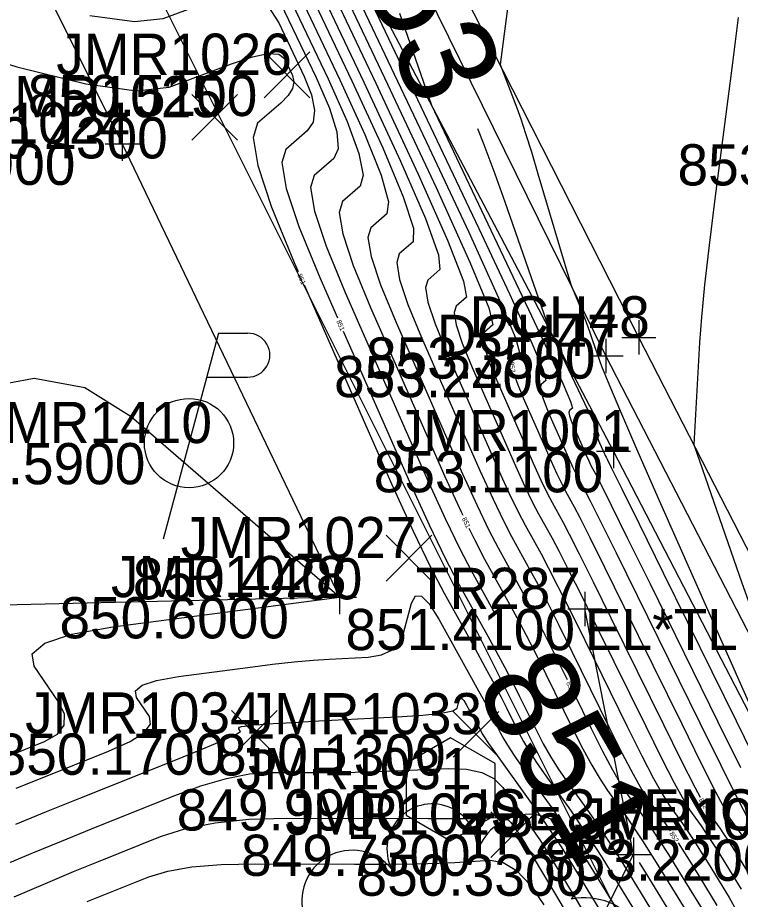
# Model space of a CAD drawing. Extents: x 1654928 to 1810050, y 486881 to 626330.
# Drawn here: x 1801396.23 to 1801417.31, y 489814.52 to 489840.21 of the extents above; entities that cross this region are included whole.
import ezdxf

# ---------------------------------------------------------------- set-up
doc = ezdxf.new("R2010")
doc.units = 0
for name, color, linetype in [('DT_X_Contour_Major', 7, 'Continuous'), ('DT_X_Contour_Minor', 7, 'Continuous'), ('PV_X_EOP', 7, 'Continuous'), ('PV_X_Shoulder', 7, 'Continuous'), ('RD_X_Cells', 7, 'Continuous'), ('RD_X_Fence', 7, 'Continuous'), ('RW_X_Esmt_SH', 7, 'Continuous'), ('SV_X_Break_Lines', 7, 'Continuous'), ('SV_X_Random_Point', 7, 'Continuous'), ('SV_X_Shot_Marker', 7, 'Continuous'), ('SV_X_Text_Comment', 7, 'Continuous'), ('SV_X_Text_Elevation', 7, 'Continuous'), ('SV_X_Text_Name', 7, 'Continuous'), ('UT_X_Electric_Cells', 7, 'Continuous'), ('UT_X_Telecom', 7, 'Continuous'), ('VG_X_Cells', 7, 'Continuous')]:
    doc.layers.add(name, color=color, linetype=linetype)

msp = doc.modelspace()

# ---------------------------------------------------------------- linework, layer by layer
at = {"layer": 'DT_X_Contour_Major'}
for points in [[(1801402.845, 489846.354), (1801406.672, 489838.301), (1801407.913, 489835.647), (1801408.768, 489833.723), (1801409.235, 489832.53), (1801409.316, 489832.067), (1801409.015, 489831.806), (1801408.96, 489831.621), (1801409.021, 489831.26), (1801409.197, 489830.724), (1801409.49, 489830.013), (1801410.425, 489827.883), (1801410.75, 489827.151), (1801411.025, 489826.552), (1801411.248, 489826.086), (1801411.422, 489825.753), (1801411.816, 489825.042), (1801412.01, 489824.677), (1801412.298, 489824.115), (1801412.678, 489823.356), (1801413.151, 489822.399), (1801414.537, 489819.586), (1801415.007, 489818.641), (1801415.379, 489817.916), (1801415.652, 489817.412), (1801415.826, 489817.127), (1801416.159, 489816.662), (1801416.292, 489816.47), (1801416.444, 489816.241), (1801416.614, 489815.975), (1801416.802, 489815.672), (1801417.327, 489814.817)], [(1801403.678, 489841.112), (1801404.937, 489838.464), (1801405.323, 489837.572), (1801405.537, 489836.882), (1801405.58, 489836.393), (1801405.451, 489836.107), (1801404.879, 489835.612), (1801404.774, 489835.259), (1801404.89, 489834.574), (1801405.226, 489833.555), (1801405.782, 489832.203), (1801407.559, 489828.154), (1801408.177, 489826.762), (1801408.699, 489825.623), (1801409.125, 489824.737), (1801409.454, 489824.104), (1801410.15, 489822.85)], [(1801409.638, 489836.984), (1801409.823, 489836.512), (1801410.145, 489835.658), (1801410.436, 489834.847), (1801411.723, 489831.16), (1801412.759, 489828.98), (1801412.952, 489828.57), (1801413.087, 489828.275), (1801413.163, 489828.094), (1801413.181, 489828.027), (1801413.151, 489828.001), (1801413.145, 489827.983), (1801413.152, 489827.947), (1801413.169, 489827.894), (1801413.198, 489827.823), (1801413.291, 489827.612), (1801413.323, 489827.54), (1801413.35, 489827.48), (1801413.372, 489827.434), (1801413.389, 489827.401), (1801413.429, 489827.331), (1801413.541, 489827.105), (1801413.849, 489826.481), (1801414.353, 489825.459), (1801415.053, 489824.039), (1801417.18, 489819.721), (1801417.881, 489818.3)], [(1801395.757, 489815.49), (1801396.632, 489815.859), (1801397.51, 489816.221), (1801398.389, 489816.577), (1801400.738, 489817.517), (1801401.576, 489817.826), (1801402.326, 489818.046), (1801402.989, 489818.177), (1801403.566, 489818.22), (1801404.987, 489818.217), (1801405.527, 489818.219), (1801406.079, 489818.228), (1801406.645, 489818.243), (1801407.223, 489818.265), (1801408.782, 489818.332), (1801409.321, 489818.316), (1801409.766, 489818.22), (1801410.119, 489818.044), (1801410.379, 489817.786), (1801410.947, 489816.991), (1801411.148, 489816.708), (1801411.324, 489816.452), (1801411.474, 489816.225), (1801411.6, 489816.027), (1801412.042, 489815.305), (1801412.236, 489814.982), (1801412.484, 489814.567), (1801414.318, 489811.48)], [(1801414.354, 489815.595), (1801414.607, 489815.188), (1801415.563, 489813.631)]]:
    msp.add_lwpolyline(points, dxfattribs=at)
at = {"layer": 'DT_X_Contour_Minor'}
for points in [[(1801401.454, 489850.675), (1801408.141, 489836.605), (1801409.386, 489833.96), (1801410.254, 489832.052), (1801410.746, 489830.882), (1801410.862, 489830.451), (1801410.669, 489830.284), (1801410.655, 489830.236)], [(1801402.678, 489847.402), (1801407.019, 489838.269), (1801408.431, 489835.262), (1801409.414, 489833.091), (1801409.967, 489831.757), (1801410.089, 489831.259), (1801409.842, 489831.045), (1801409.797, 489830.893), (1801409.847, 489830.598), (1801409.992, 489830.158), (1801410.232, 489829.575), (1801410.998, 489827.829), (1801411.265, 489827.228), (1801411.49, 489826.737), (1801411.673, 489826.355), (1801411.815, 489826.082), (1801412.139, 489825.5), (1801412.317, 489825.163), (1801412.608, 489824.588), (1801413.013, 489823.777), (1801413.532, 489822.727), (1801415.066, 489819.613), (1801415.582, 489818.573), (1801415.981, 489817.788), (1801416.132, 489817.503)], [(1801403.012, 489845.306), (1801406.325, 489838.334), (1801407.395, 489836.032), (1801408.122, 489834.355), (1801408.504, 489833.302), (1801408.543, 489832.875), (1801408.188, 489832.567), (1801408.123, 489832.349), (1801408.194, 489831.923), (1801408.403, 489831.291), (1801408.748, 489830.451), (1801409.852, 489827.937), (1801410.235, 489827.073), (1801410.559, 489826.366), (1801410.824, 489825.816), (1801411.028, 489825.423), (1801411.494, 489824.585), (1801411.704, 489824.192), (1801411.987, 489823.642), (1801412.343, 489822.935), (1801412.771, 489822.071), (1801414.008, 489819.559), (1801414.433, 489818.709), (1801414.777, 489818.044), (1801415.042, 489817.564), (1801415.227, 489817.269), (1801415.614, 489816.728), (1801415.77, 489816.504), (1801415.947, 489816.237), (1801416.144, 489815.927), (1801416.363, 489815.575), (1801416.974, 489814.58), (1801417.187, 489814.207)], [(1801411.036, 489844.506), (1801410.3, 489838.843), (1801410.785, 489837.583), (1801410.902, 489837.26), (1801411.043, 489836.832), (1801411.211, 489836.298), (1801411.403, 489835.659), (1801412.362, 489832.432), (1801412.67, 489831.685), (1801412.74, 489831.51), (1801412.818, 489831.305), (1801412.904, 489831.071), (1801412.998, 489830.806), (1801413.259, 489830.06), (1801413.437, 489829.606), (1801413.777, 489828.802), (1801414.278, 489827.649), (1801414.941, 489826.147), (1801418.411, 489818.322)], [(1801403.178, 489844.257), (1801405.978, 489838.367), (1801406.877, 489836.417), (1801407.476, 489834.987), (1801407.773, 489834.075), (1801407.77, 489833.683), (1801407.36, 489833.328), (1801407.285, 489833.076), (1801407.368, 489832.586), (1801407.609, 489831.857), (1801408.007, 489830.889), (1801409.278, 489827.991), (1801409.721, 489826.995), (1801410.094, 489826.18), (1801410.399, 489825.546), (1801410.635, 489825.093), (1801411.171, 489824.127), (1801411.398, 489823.706), (1801411.677, 489823.169), (1801412.008, 489822.514), (1801412.39, 489821.743), (1801413.48, 489819.532), (1801413.858, 489818.777), (1801414.175, 489818.172), (1801414.432, 489817.716), (1801414.628, 489817.41), (1801415.07, 489816.793), (1801415.247, 489816.537), (1801415.257, 489816.522)], [(1801404.877, 489844.17), (1801409.68, 489834.064), (1801410.574, 489832.163), (1801411.198, 489830.793), (1801411.552, 489829.953), (1801411.635, 489829.643), (1801411.496, 489829.523), (1801411.471, 489829.438), (1801411.499, 489829.272), (1801411.58, 489829.026), (1801411.715, 489828.699), (1801412.144, 489827.72), (1801412.294, 489827.384), (1801412.42, 489827.109), (1801412.523, 489826.895), (1801412.602, 489826.742), (1801412.784, 489826.415), (1801412.929, 489826.134), (1801413.229, 489825.535), (1801413.683, 489824.618), (1801416.123, 489819.667), (1801416.731, 489818.437), (1801417.184, 489817.532), (1801417.481, 489816.954)], [(1801403.345, 489843.209), (1801405.631, 489838.399), (1801406.359, 489836.802), (1801406.83, 489835.618), (1801407.042, 489834.848), (1801406.997, 489834.491), (1801406.533, 489834.089), (1801406.448, 489833.804), (1801406.542, 489833.248), (1801406.814, 489832.423), (1801407.265, 489831.327), (1801408.705, 489828.046), (1801409.206, 489826.917), (1801409.629, 489825.994), (1801409.974, 489825.276), (1801410.241, 489824.764), (1801410.849, 489823.669), (1801411.092, 489823.221), (1801411.367, 489822.695), (1801411.673, 489822.094), (1801412.01, 489821.415), (1801412.251, 489820.927)], [(1801403.512, 489842.161), (1801405.284, 489838.432), (1801405.841, 489837.187), (1801406.184, 489836.25), (1801406.311, 489835.621), (1801406.224, 489835.299), (1801405.706, 489834.851), (1801405.611, 489834.532), (1801405.716, 489833.911), (1801406.02, 489832.989), (1801406.523, 489831.765), (1801408.132, 489828.1), (1801408.692, 489826.84), (1801409.164, 489825.809), (1801409.211, 489825.712)], [(1801386.203, 489842.133), (1801393.676, 489839.584), (1801396.214, 489838.78), (1801398.222, 489838.279), (1801399.7, 489838.08), (1801400.648, 489838.185), (1801402.471, 489838.868), (1801403.08, 489839.07), (1801403.54, 489839.161), (1801403.85, 489839.143), (1801404.012, 489839.016), (1801404.243, 489838.529), (1801404.287, 489838.342), (1801404.245, 489838.145), (1801404.118, 489837.939), (1801403.905, 489837.723), (1801403.224, 489837.134), (1801403.1, 489836.715), (1801403.237, 489835.899), (1801403.637, 489834.687), (1801404.299, 489833.079), (1801404.416, 489832.813)], [(1801398.342, 489840.27), (1801399.643, 489840.095), (1801400.478, 489840.187), (1801402.083, 489840.789)], [(1801403.525, 489840.55), (1801403.845, 489840.064), (1801404.59, 489838.497), (1801404.805, 489837.957), (1801404.891, 489837.514), (1801404.849, 489837.166), (1801404.678, 489836.915), (1801404.051, 489836.373), (1801403.937, 489835.987), (1801404.064, 489835.237), (1801404.431, 489834.121), (1801405.04, 489832.641), (1801405.556, 489831.466)], [(1801407.365, 489840.342), (1801408.3, 489837.665), (1801411.22, 489831.522), (1801411.763, 489830.367), (1801412.142, 489829.534), (1801412.357, 489829.023), (1801412.408, 489828.835), (1801412.324, 489828.762), (1801412.308, 489828.71), (1801412.325, 489828.609), (1801412.375, 489828.46), (1801412.456, 489828.261), (1801412.717, 489827.666), (1801412.808, 489827.462), (1801412.885, 489827.294), (1801412.948, 489827.164), (1801412.996, 489827.071), (1801413.106, 489826.873), (1801413.235, 489826.62), (1801413.539, 489826.008), (1801414.018, 489825.039), (1801414.673, 489823.711), (1801416.651, 489819.694), (1801417.306, 489818.368)], [(1801417.236, 489840.216), (1801417.068, 489838.815), (1801416.563, 489834.932), (1801416.393, 489833.578), (1801416.261, 489832.429), (1801416.168, 489831.486), (1801416.113, 489830.747), (1801415.947, 489827.777), (1801417.104, 489824.439), (1801417.348, 489823.746), (1801417.583, 489823.097), (1801417.811, 489822.491), (1801418.03, 489821.93), (1801419.035, 489819.412), (1801421.198, 489814.495)], [(1801404.584, 489832.428), (1801406.412, 489828.262), (1801407.148, 489826.606), (1801407.769, 489825.252), (1801408.275, 489824.198), (1801408.667, 489823.445), (1801409.559, 489821.839), (1801409.868, 489821.278), (1801410.126, 489820.803), (1801410.333, 489820.411), (1801410.489, 489820.104), (1801410.837, 489819.396), (1801410.985, 489819.118), (1801411.167, 489818.812), (1801411.383, 489818.478), (1801411.634, 489818.118), (1801412.348, 489817.12), (1801412.628, 489816.718), (1801412.932, 489816.261), (1801413.261, 489815.749), (1801413.613, 489815.183), (1801414.586, 489813.598)], [(1801405.725, 489831.081), (1801406.986, 489828.208), (1801407.662, 489826.684), (1801408.234, 489825.437), (1801408.7, 489824.467), (1801409.06, 489823.775), (1801409.881, 489822.296), (1801410.174, 489821.764), (1801410.436, 489821.276), (1801410.668, 489820.832), (1801410.869, 489820.432), (1801411.366, 489819.424), (1801411.559, 489819.05), (1801411.769, 489818.684), (1801411.993, 489818.326), (1801412.233, 489817.976), (1801412.893, 489817.054), (1801413.158, 489816.672), (1801413.459, 489816.218), (1801413.796, 489815.69), (1801414.168, 489815.091), (1801415.553, 489812.833)], [(1801410.708, 489829.828), (1801410.786, 489829.592), (1801410.973, 489829.137), (1801411.571, 489827.775), (1801411.779, 489827.306), (1801411.955, 489826.923), (1801412.098, 489826.625), (1801412.209, 489826.412), (1801412.461, 489825.958), (1801412.623, 489825.648), (1801412.918, 489825.062), (1801413.348, 489824.197), (1801413.912, 489823.055), (1801415.594, 489819.64), (1801416.157, 489818.505), (1801416.582, 489817.66), (1801416.871, 489817.107), (1801417.024, 489816.844), (1801417.247, 489816.532), (1801417.337, 489816.402)], [(1801394.166, 489817.962), (1801394.506, 489818.108), (1801394.884, 489818.266), (1801395.3, 489818.436), (1801397.013, 489819.124), (1801397.393, 489819.338), (1801397.589, 489819.601), (1801397.599, 489819.915), (1801397.425, 489820.278), (1801396.714, 489821.313), (1801396.658, 489821.676), (1801397.022, 489821.988), (1801397.807, 489822.25), (1801399.012, 489822.461), (1801405.615, 489823.327), (1801399.547, 489828.578), (1801398.188, 489829.421), (1801396.712, 489829.697), (1801395.991, 489829.566)], [(1801409.393, 489825.333), (1801409.549, 489825.007), (1801409.847, 489824.434), (1801410.526, 489823.212), (1801410.786, 489822.735), (1801411.056, 489822.222), (1801411.338, 489821.673), (1801411.63, 489821.088), (1801412.423, 489819.478), (1801412.709, 489818.913), (1801412.972, 489818.428), (1801413.213, 489818.021), (1801413.43, 489817.693), (1801413.981, 489816.924), (1801414.203, 489816.605), (1801414.454, 489816.225), (1801414.735, 489815.785), (1801415.046, 489815.285), (1801415.915, 489813.868)], [(1801396.187, 489817.758), (1801396.9, 489818.046), (1801398.88, 489818.838), (1801399.511, 489819.124), (1801399.922, 489819.388), (1801400.111, 489819.629), (1801400.079, 489819.848), (1801399.699, 489820.402), (1801399.669, 489820.596), (1801399.864, 489820.763), (1801400.283, 489820.903), (1801400.928, 489821.015), (1801402.946, 489821.28), (1801403.662, 489821.37), (1801404.295, 489821.44), (1801404.846, 489821.491), (1801405.315, 489821.523), (1801406.454, 489821.583), (1801406.839, 489821.643), (1801407.139, 489821.779), (1801407.354, 489821.991), (1801407.484, 489822.279), (1801407.717, 489823.149), (1801407.833, 489823.364), (1801408.004, 489823.359), (1801408.23, 489823.132), (1801408.512, 489822.685), (1801409.619, 489820.689), (1801409.841, 489820.283), (1801410.004, 489819.979), (1801410.108, 489819.776), (1801410.308, 489819.369), (1801410.41, 489819.186), (1801410.565, 489818.94), (1801410.773, 489818.631), (1801411.035, 489818.259), (1801411.804, 489817.185), (1801412.091, 489816.775), (1801412.377, 489816.352), (1801412.66, 489815.915), (1801412.942, 489815.464), (1801413.691, 489814.244)], [(1801396.183, 489816.715), (1801397.074, 489817.08), (1801398.046, 489817.472), (1801400.746, 489818.553), (1801401.63, 489818.911), (1801402.255, 489819.174), (1801402.623, 489819.343), (1801402.734, 489819.418), (1801402.684, 489819.49), (1801402.68, 489819.515), (1801402.706, 489819.537), (1801402.76, 489819.555), (1801402.844, 489819.57), (1801403.108, 489819.604), (1801403.301, 489819.621), (1801403.683, 489819.646), (1801404.254, 489819.679), (1801405.014, 489819.72), (1801407.293, 489819.838), (1801408.044, 489819.888), (1801408.586, 489819.948), (1801408.921, 489820.017), (1801409.048, 489820.097), (1801409.108, 489820.322), (1801409.138, 489820.378), (1801409.182, 489820.377), (1801409.241, 489820.318), (1801409.314, 489820.202), (1801409.528, 489819.816), (1801409.601, 489819.685), (1801409.659, 489819.579), (1801409.728, 489819.448), (1801409.78, 489819.342), (1801409.835, 489819.254), (1801409.963, 489819.067), (1801410.164, 489818.783), (1801411.26, 489817.25), (1801411.554, 489816.833), (1801411.821, 489816.443), (1801412.06, 489816.08), (1801412.271, 489815.745), (1801412.998, 489814.559), (1801413.21, 489814.211)], [(1801412.436, 489820.551), (1801412.951, 489819.505), (1801413.283, 489818.845), (1801413.574, 489818.3), (1801413.822, 489817.869), (1801414.029, 489817.552), (1801414.526, 489816.858), (1801414.725, 489816.571), (1801414.951, 489816.229), (1801415.205, 489815.833), (1801415.485, 489815.382), (1801416.268, 489814.106)], [(1801416.335, 489817.136), (1801416.425, 489816.986), (1801416.703, 489816.597), (1801416.815, 489816.436), (1801416.942, 489816.245), (1801417.084, 489816.022), (1801417.241, 489815.769), (1801417.68, 489815.054), (1801417.84, 489814.756), (1801417.994, 489814.399)], [(1801396.132, 489814.601), (1801397.046, 489814.989), (1801397.865, 489815.331), (1801398.591, 489815.625), (1801400.4, 489816.35), (1801401.138, 489816.587), (1801401.997, 489816.756), (1801402.977, 489816.856), (1801404.077, 489816.887), (1801408.205, 489816.879), (1801408.987, 489816.88), (1801409.516, 489816.883), (1801409.794, 489816.888), (1801410.198, 489816.906), (1801410.338, 489816.902), (1801410.453, 489816.877), (1801410.545, 489816.831), (1801410.612, 489816.764), (1801410.76, 489816.558), (1801410.812, 489816.485), (1801410.857, 489816.418), (1801410.896, 489816.36), (1801410.929, 489816.308), (1801411.007, 489816.181), (1801411.262, 489815.754), (1801411.537, 489815.291), (1801411.911, 489814.663), (1801413.881, 489811.346)], [(1801415.488, 489816.172), (1801415.675, 489815.88), (1801415.924, 489815.479), (1801416.621, 489814.343)], [(1801398.258, 489814.456), (1801398.792, 489814.674), (1801400.061, 489815.182), (1801400.613, 489815.348), (1801401.315, 489815.466), (1801402.169, 489815.536), (1801403.175, 489815.558), (1801406.056, 489815.551), (1801407.05, 489815.552), (1801407.869, 489815.56), (1801408.514, 489815.574), (1801408.984, 489815.596), (1801410.006, 489815.661), (1801410.391, 489815.598), (1801410.781, 489815.36), (1801411.175, 489814.948), (1801411.574, 489814.361)]]:
    msp.add_lwpolyline(points, dxfattribs=at)
at = {"layer": 'PV_X_EOP'}
msp.add_lwpolyline([(1801513.785, 489634.043), (1801503.26, 489654.965), (1801492.692, 489675.84), (1801481.803, 489697.704), (1801472.078, 489717.629), (1801460.782, 489739.414), (1801448.005, 489764.97), (1801436.553, 489786.89), (1801425.237, 489809.697), (1801414.345, 489830.894), (1801402.21, 489854.742), (1801391.781, 489876.056), (1801380.008, 489899.32), (1801369.395, 489920.807), (1801356.62, 489946.308), (1801346.845, 489965.404), (1801335.257, 489988.444)], dxfattribs=at)
at = {"layer": 'PV_X_Shoulder'}
msp.add_lwpolyline([(1801513.053, 489633.484), (1801502.425, 489654.401), (1801492.155, 489675.438), (1801481.048, 489697.245), (1801471.095, 489717.056), (1801459.974, 489738.844), (1801446.996, 489764.517), (1801435.938, 489786.184), (1801424.33, 489809.156), (1801413.386, 489830.353), (1801401.606, 489854.259), (1801390.811, 489875.349), (1801379.301, 489898.985), (1801368.607, 489920.204), (1801355.561, 489945.921), (1801346.174, 489964.922), (1801334.144, 489988.199)], dxfattribs=at)
at = {"layer": 'RD_X_Cells'}
msp.add_lwpolyline([(1801407.557, 489816.979), (1801408.855, 489816.229), (1801410.153, 489816.979), (1801410.153, 489818.479), (1801408.855, 489819.229), (1801407.557, 489818.479), (1801407.557, 489816.979)], dxfattribs=at)
at = {"layer": 'RD_X_Fence'}
msp.add_lwpolyline([(1801327.157, 489980.825), (1801341.337, 489952.815), (1801353.978, 489927.719), (1801368.649, 489898.399), (1801382.749, 489869.731), (1801399.284, 489836.538), (1801405.615, 489823.327), (1801393.757, 489823.044), (1801375.98, 489823.449), (1801361.092, 489823.97), (1801335.059, 489824.221), (1801306.244, 489824.992)], dxfattribs=at)
at = {"layer": 'RW_X_Esmt_SH'}
msp.add_line((1801533.563, 489574.54), (1801308.538, 490024.454), dxfattribs=at)
at = {"layer": 'SV_X_Break_Lines'}
msp.add_lwpolyline([(1801419.479, 489816.264), (1801413.606, 489827.582), (1801399.229, 489854.903), (1801388.205, 489875.792), (1801377.391, 489897.446), (1801365.991, 489920.501), (1801353.319, 489946.375), (1801342.526, 489967.898), (1801332.595, 489987.823)], dxfattribs=at)
at = {"layer": 'SV_X_Random_Point'}
for p, q in [((1801403.42, 489837.876), (1801404.753, 489839.211)), ((1801403.42, 489839.211), (1801404.753, 489837.876)), ((1801401.309, 489836.641), (1801402.642, 489837.976)), ((1801401.309, 489837.976), (1801402.642, 489836.641)), ((1801406.974, 489823.795), (1801408.307, 489825.13)), ((1801406.974, 489825.13), (1801408.307, 489823.795)), ((1801402.465, 489818.686), (1801403.798, 489820.021)), ((1801402.465, 489820.021), (1801403.798, 489818.686)), ((1801408.928, 489818.665), (1801410.261, 489820)), ((1801408.928, 489820), (1801410.261, 489818.665)), ((1801410.027, 489815.739), (1801411.361, 489817.074)), ((1801410.027, 489817.074), (1801411.361, 489815.739))]:
    msp.add_line(p, q, dxfattribs=at)
at = {"layer": 'SV_X_Shot_Marker'}
for p, q in [((1801399.284, 489837.038), (1801399.284, 489836.038)), ((1801398.784, 489836.538), (1801399.784, 489836.538)), ((1801399.284, 489836.538), (1801399.284, 489836.538)), ((1801414.345, 489831.394), (1801414.345, 489830.394)), ((1801413.386, 489830.853), (1801413.386, 489829.853)), ((1801413.845, 489830.894), (1801414.845, 489830.894)), ((1801414.345, 489830.894), (1801414.345, 489830.894)), ((1801412.886, 489830.353), (1801413.886, 489830.353)), ((1801413.386, 489830.353), (1801413.386, 489830.353)), ((1801413.606, 489828.082), (1801413.606, 489827.082)), ((1801413.106, 489827.582), (1801414.106, 489827.582)), ((1801413.606, 489827.582), (1801413.606, 489827.582)), ((1801405.615, 489823.827), (1801405.615, 489822.827)), ((1801412.772, 489823.484), (1801412.772, 489822.484)), ((1801405.115, 489823.327), (1801406.115, 489823.327)), ((1801405.615, 489823.327), (1801405.615, 489823.327)), ((1801412.272, 489822.984), (1801413.272, 489822.984)), ((1801412.772, 489822.984), (1801412.772, 489822.984)), ((1801414.185, 489816.328), (1801414.185, 489815.328)), ((1801413.685, 489815.828), (1801414.685, 489815.828)), ((1801414.185, 489815.828), (1801414.185, 489815.828))]:
    msp.add_line(p, q, dxfattribs=at)
at = {"layer": 'UT_X_Electric_Cells'}
for p, q in [((1801402.086, 489831.016), (1801400.48, 489825.016)), ((1801402.086, 489831.016), (1801402.936, 489831.016)), ((1801401.745, 489829.741), (1801402.936, 489829.741))]:
    msp.add_line(p, q, dxfattribs=at)
msp.add_circle((1801401.23, 489827.816), 1.3, dxfattribs=at)
msp.add_arc((1801402.949, 489830.378), 0.638, 268.8767, 91.1233, dxfattribs=at)
at = {"layer": 'UT_X_Telecom'}
msp.add_lwpolyline([(1801441.137, 489770.528), (1801431.587, 489788.879), (1801425.735, 489794.702), (1801417.855, 489797.975), (1801411.771, 489811.027), (1801414.185, 489815.828), (1801412.772, 489822.984)], dxfattribs=at)
at = {"layer": 'VG_X_Cells'}
for centre, radius, start, end in [((1801408.317, 489815.986), 1.317, 354.0047, 205.9741), ((1801411.127, 489815.448), 1.553, 323.83, 165.0376), ((1801405.991, 489814.483), 1.471, 39.0625, 279.5412), ((1801412.761, 489812.655), 1.915, 259.1453, 101.4596)]:
    msp.add_arc(centre, radius, start, end, dxfattribs=at)

# ---------------------------------------------------------------- texts
at = {"layer": 'DT_X_Contour_Major'}
for s, rotation, p in [('853', 290.9204, (1801405.602, 489843.347)), ('851', 300.0904, (1801409.522, 489820.712))]:
    msp.add_text(s, height=2.8, rotation=rotation, dxfattribs=at).set_placement(p)
at = {"layer": 'DT_X_Contour_Minor'}
for s, rotation, p in [('851', 293.6935, (1801404.382, 489832.714)), ('851', 293.6935, (1801405.523, 489831.367)), ('852', 277.4189, (1801410.567, 489830.18)), ('851', 295.6601, (1801409.181, 489825.612)), ('851', 296.2232, (1801412.222, 489820.827)), ('852', 298.9431, (1801416.092, 489817.423)), ('852', 303.3523, (1801415.228, 489816.441))]:
    msp.add_text(s, height=0.14, rotation=rotation, dxfattribs=at).set_placement(p)
at = {"layer": 'SV_X_Text_Comment'}
for s, p in [('EL*TL', (1801412.772, 489821.784)), ('USE? FENCE SIZE? 1" MAT? STEEL', (1801408.855, 489816.529))]:
    msp.add_text(s, height=1.2, dxfattribs=at).set_placement(p)
at = {"layer": 'SV_X_Text_Elevation'}
for s, p in [('850.5100', (1801396.529, 489837.344)), ('850.4300', (1801393.916, 489836.109)), ('850.4900', (1801391.225, 489835.338)), ('853.6000', (1801415.472, 489835.322)), ('853.3500', (1801406.39, 489829.694)), ('853.2400', (1801405.459, 489829.153)), ('849.5900', (1801393.265, 489826.616)), ('853.1100', (1801406.615, 489826.382)), ('850.4400', (1801399.591, 489823.263)), ('850.6000', (1801397.452, 489822.127)), ('851.4100', (1801405.791, 489821.784)), ('850.1700', (1801395.593, 489818.153)), ('850.1300', (1801402.018, 489818.133)), ('849.9900', (1801400.871, 489816.529)), ('849.7300', (1801402.748, 489815.207)), ('853.2200', (1801411.58, 489815.064)), ('850.3300', (1801406.116, 489814.628))]:
    msp.add_text(s, height=1.2, dxfattribs=at).set_placement(p)
at = {"layer": 'SV_X_Text_Name'}
for s, p in [('JMR1026', (1801397.36, 489838.544)), ('JMR1025', (1801395.325, 489837.309)), ('JMR1024', (1801392.643, 489836.538)), ('DCH48', (1801409.404, 489830.894)), ('DCH47', (1801408.455, 489830.353)), ('JMR1410', (1801395.033, 489827.816)), ('JMR1001', (1801407.256, 489827.582)), ('JMR1027', (1801400.989, 489824.463)), ('JMR1028', (1801398.955, 489823.327)), ('TR287', (1801407.84, 489822.984)), ('JMR1034', (1801396.452, 489819.353)), ('JMR1033', (1801402.906, 489819.333)), ('JMR1031', (1801402.6, 489817.729)), ('JMR1029', (1801404.034, 489816.407)), ('JMR1000', (1801412.592, 489816.264)), ('TR286', (1801409.178, 489815.828))]:
    msp.add_text(s, height=1.2, dxfattribs=at).set_placement(p)

doc.saveas('drawing.dxf')
